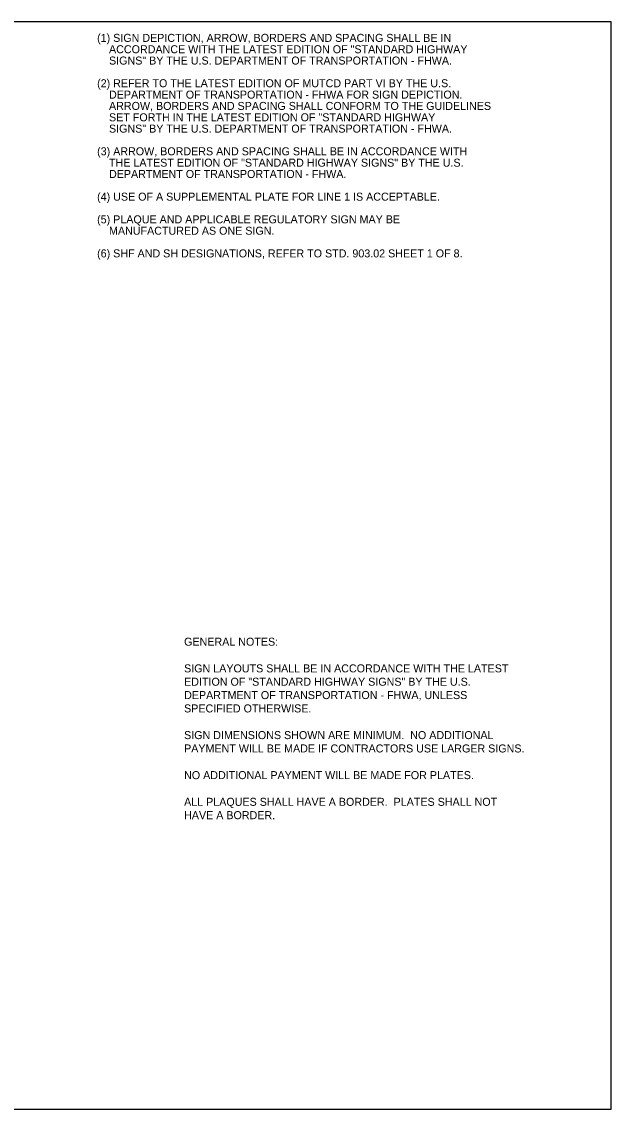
# Model space of a CAD drawing. Extents: x -439.1 to -407.9, y -458.1 to -437.7.
# Drawn here: x -418.9 to -407.86, y -458.05 to -437.68 of the extents above; entities that cross this region are included whole.
import ezdxf

# ---------------------------------------------------------------- set-up
doc = ezdxf.new("R2010")
doc.units = 0
for name, color, linetype in [('Draft_Named_Boundary', 7, 'Continuous'), ('Level 4', 7, 'Continuous'), ('Level 45', 7, 'Continuous')]:
    doc.layers.add(name, color=color, linetype=linetype)

msp = doc.modelspace()

# ---------------------------------------------------------------- linework, layer by layer
at = {"layer": 'Draft_Named_Boundary'}
msp.add_lwpolyline([(-439.109, -458.051), (-407.859, -458.051), (-407.859, -437.676), (-439.109, -437.676)], close=True, dxfattribs=at)

# ---------------------------------------------------------------- texts
at = {"layer": 'Level 4'}
for s, p in [('(1) SIGN DEPICTION, ARROW, BORDERS AND SPACING SHALL BE IN ', (-417.488, -438.053)), ('    ACCORDANCE WITH THE LATEST EDITION OF "STANDARD HIGHWAY ', (-417.488, -438.266)), ('    SIGNS" BY THE U.S. DEPARTMENT OF TRANSPORTATION - FHWA.', (-417.488, -438.478)), ('(2) REFER TO THE LATEST EDITION OF MUTCD PART VI BY THE U.S. ', (-417.488, -438.903)), ('    DEPARTMENT OF TRANSPORTATION - FHWA FOR SIGN DEPICTION. ', (-417.488, -439.116)), ('    ARROW, BORDERS AND SPACING SHALL CONFORM TO THE GUIDELINES ', (-417.488, -439.328)), ('    SET FORTH IN THE LATEST EDITION OF "STANDARD HIGHWAY ', (-417.488, -439.541)), ('    SIGNS" BY THE U.S. DEPARTMENT OF TRANSPORTATION - FHWA.', (-417.488, -439.753)), ('(3) ARROW, BORDERS AND SPACING SHALL BE IN ACCORDANCE WITH ', (-417.488, -440.178)), ('    THE LATEST EDITION OF "STANDARD HIGHWAY SIGNS" BY THE U.S. ', (-417.488, -440.391)), ('    DEPARTMENT OF TRANSPORTATION - FHWA.', (-417.488, -440.603)), ('(4) USE OF A SUPPLEMENTAL PLATE FOR LINE 1 IS ACCEPTABLE.', (-417.488, -441.028)), ('(5) PLAQUE AND APPLICABLE REGULATORY SIGN MAY BE ', (-417.488, -441.453)), ('    MANUFACTURED AS ONE SIGN.', (-417.488, -441.666)), ('(6) SHF AND SH DESIGNATIONS, REFER TO STD. 903.02 SHEET 1 OF 8.', (-417.488, -442.091))]:
    msp.add_text(s, height=0.15, dxfattribs=at).set_placement(p)
at = {"layer": 'Level 45'}
for s, p in [('GENERAL NOTES:', (-415.859, -449.366)), ('SIGN LAYOUTS SHALL BE IN ACCORDANCE WITH THE LATEST ', (-415.859, -449.866)), ('EDITION OF "STANDARD HIGHWAY SIGNS" BY THE U.S. ', (-415.859, -450.116)), ('DEPARTMENT OF TRANSPORTATION - FHWA, UNLESS ', (-415.859, -450.366)), ('SPECIFIED OTHERWISE.', (-415.859, -450.616)), ('SIGN DIMENSIONS SHOWN ARE MINIMUM.  NO ADDITIONAL ', (-415.859, -451.116)), ('PAYMENT WILL BE MADE IF CONTRACTORS USE LARGER SIGNS.', (-415.859, -451.366)), ('NO ADDITIONAL PAYMENT WILL BE MADE FOR PLATES. ', (-415.859, -451.866)), ('ALL PLAQUES SHALL HAVE A BORDER.  PLATES SHALL NOT ', (-415.859, -452.366)), ('HAVE A BORDER.', (-415.859, -452.616))]:
    msp.add_text(s, height=0.15, dxfattribs=at).set_placement(p)

doc.saveas('drawing.dxf')
